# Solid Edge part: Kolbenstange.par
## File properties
Username: bmolnar
Dokumentum tartalom típus: 0
Author: bmolnar
Last saved by: bmolnar
Revision: 81
Sűrűség: 0,000 kg/m^3
Pontosság: 0,990
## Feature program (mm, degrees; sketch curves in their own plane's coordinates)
base feature "unnamed BaseFeature 1"
sketch for "unnamed Protrusion 1" plane through (18.4, 0, 0) normal (1, 0, 0) x-axis (0, 1, 0)
  circle centre (0, 0) radius 8
extrude "unnamed Protrusion 1" add finite 19.7 along +normal
sketch for "Kihúzás_2" #1 plane through (18.4, 0, 0) normal (1, 0, 0) x-axis (0, 1, 0)
  circle centre (0, 0) radius 4
sketch for "Kihúzás_2" #2 plane through (18.4, 0, 0) normal (1, 0, 0) x-axis (0, 1, 0)
  circle centre (0, 0) radius 8
extrude "Kihúzás_2" add finite 11.5 along -normal
sketch for "Furat_1" plane through (-24, 0, 0.0012) normal (-1, 0, 0) x-axis (0, 0, 1)
  hole centre (-0.0012, 0) bore radius 1.621
hole "Furat_1" nominal diameter 4 finite  VBottomAngle = 118 deg; ThreadDepth = 9 mm
chamfer "Letörés_1" setback 0.2  SetBackValue2 = 45 deg
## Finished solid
Body 1: solid body, 18 faces, 24 edges, 8 vertices.
  Faces by surface: plane 8, cylinder 5, cone 3, torus 2
  Edges by curve: circle 14, line 6, curve on surface 2, ellipse 2
Bounding box of the edges (mm; curved faces can reach further): 64.100 x 16.000 x 16.000, from (-26, -8, -8) to (38.1, 8, 8).
Cylindrical faces by radius (mm): R1.621 x2, R2.125 x1, R4 x1, R8 x1
Conical faces (half-angle, radius in mm at the cone's reference point): 45 deg R1.821 x1, 45 deg R2.225 x1, 59 deg R1.621 x1
Toroidal faces (ring radius, tube radius in mm): R1.925 r0.2 x1, R2.7 r1.3 x1
Planar faces by outward normal: +x 1, +z 1, -x 3, -z 1, oblique 2
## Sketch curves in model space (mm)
circle centre (18.4, 0, 0) radius 8
circle centre (18.4, 0, 0) radius 4
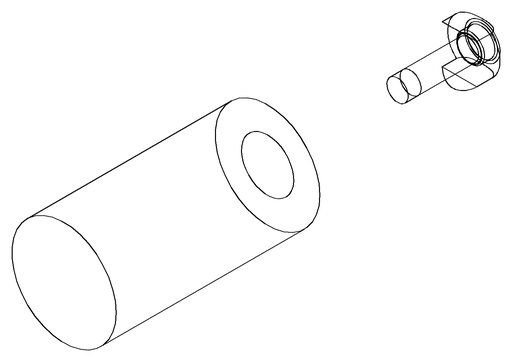
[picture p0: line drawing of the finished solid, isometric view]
